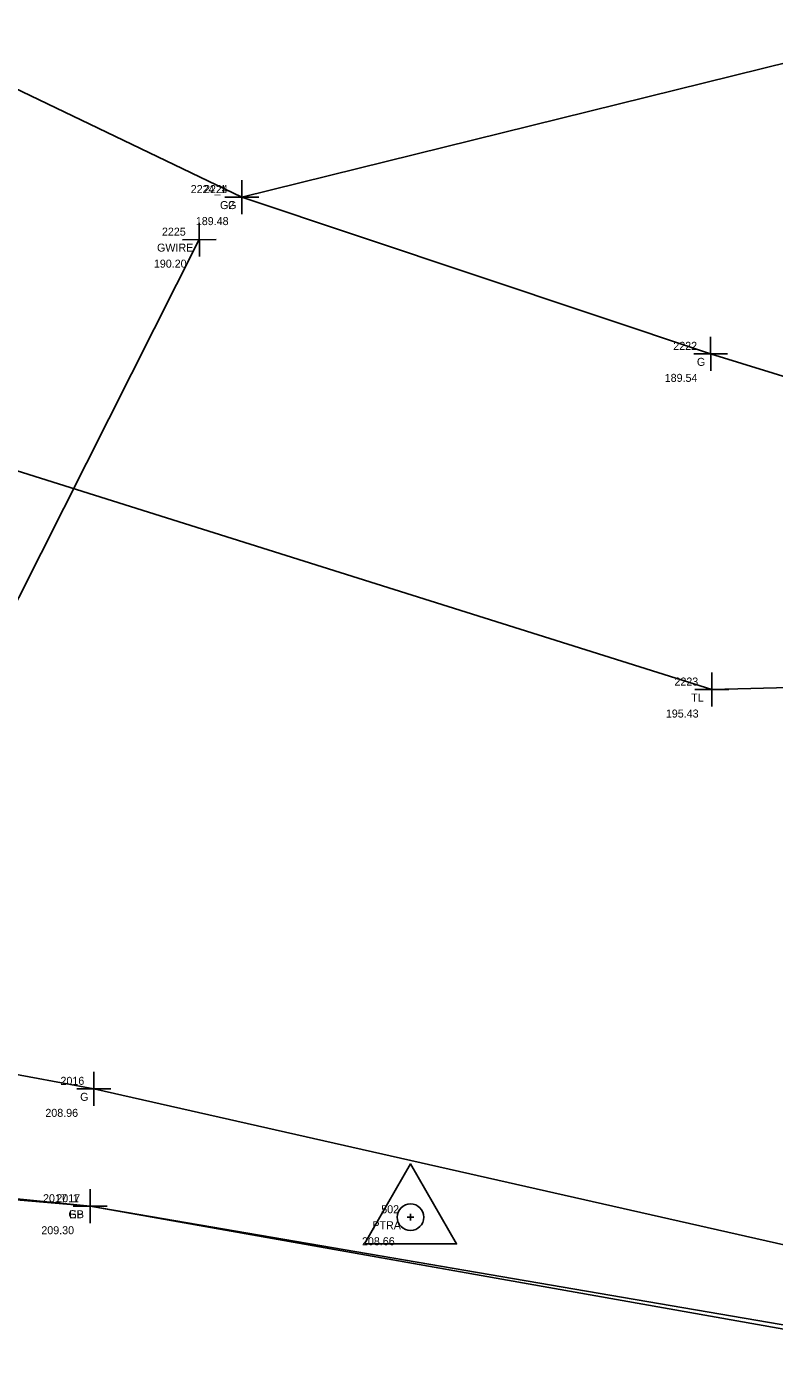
# Model space of a CAD drawing. Extents: x 1155460 to 1157069, y 590691 to 591363.
# Drawn here: x 1156504.2 to 1156532.2, y 591071.2 to 591121.6 of the extents above; entities that cross this region are included whole.
import ezdxf

# ---------------------------------------------------------------- set-up
doc = ezdxf.new("R2010")
doc.units = 0
for name, color, linetype in [('S_Control_Traverse_Point', 7, 'Continuous'), ('S_Field_Code', 7, 'Continuous'), ('S_Ground_Elevation', 7, 'Continuous'), ('S_Guardrail_Beam', 7, 'Continuous'), ('S_Point_Elevation', 7, 'Continuous'), ('S_Point_Name', 7, 'Continuous'), ('S_Roadway_Edge_Pavement', 7, 'Continuous'), ('S_Survey_Shot', 7, 'Continuous'), ('S_Trees_TreeLine', 7, 'Continuous'), ('S_Utilities_GuyWire3', 7, 'Continuous')]:
    doc.layers.add(name, color=color, linetype=linetype)

msp = doc.modelspace()

# ---------------------------------------------------------------- linework, layer by layer
at = {"layer": 'S_Control_Traverse_Point'}
for p, q in [((1156518.609, 591077.122), (1156518.609, 591076.873)), ((1156518.484, 591076.997), (1156518.734, 591076.997))]:
    msp.add_line(p, q, dxfattribs=at)
msp.add_lwpolyline([(1156516.88, 591075.999), (1156520.338, 591075.999), (1156518.609, 591078.993)], close=True, dxfattribs=at)
msp.add_circle((1156518.609, 591076.997), 0.499, dxfattribs=at)
at = {"layer": 'S_Ground_Elevation'}
for points in [[(1156994.312, 591026.354), (1156988.281, 591011.67), (1156982.157, 591006.699), (1156976.222, 591006.261), (1156935.59, 591012.529), (1156909.286, 591020.249), (1156879.276, 591021.544), (1156853.942, 591026.061), (1156816.445, 591035.649), (1156768.114, 591049.43), (1156727.412, 591060.658), (1156689.215, 591071.126), (1156661.947, 591076.437), (1156626.722, 591088.15), (1156604.058, 591089.806), (1156567.292, 591097.74), (1156529.864, 591109.36), (1156512.279, 591115.236), (1156500.524, 591120.875), (1156488.74, 591123.45), (1156482.404, 591123.727), (1156471.928, 591117.762)], [(1156611.683, 591102.465), (1156576.553, 591112.467), (1156533.986, 591120.597), (1156512.279, 591115.236)], [(1156491.913, 591082.79), (1156492.329, 591083.824), (1156495.048, 591083.957), (1156506.736, 591081.81), (1156549.796, 591072.079), (1156594.701, 591064.294), (1156643.47, 591053.992), (1156692.982, 591043.457), (1156741.529, 591033.483), (1156787.931, 591023.885), (1156837.64, 591013.684), (1156874.149, 591006.125), (1156886.147, 591007.107), (1156898.915, 591006.968), (1156908.962, 591008.2), (1156912.663, 591006.47), (1156934.598, 591002.519), (1156962.056, 590995.598), (1156977.261, 590993.461), (1156984.027, 590995.095), (1156994.336, 590998.898), (1156998.327, 591004.238), (1157007.944, 591024.295)]]:
    msp.add_lwpolyline(points, dxfattribs=at)
at = {"layer": 'S_Guardrail_Beam'}
msp.add_lwpolyline([(1156481.869, 591081.283), (1156494.59, 591078.6), (1156506.597, 591077.41), (1156549.743, 591070.029), (1156594.66, 591061.958), (1156643.746, 591051.962), (1156692.997, 591041.75), (1156740.961, 591032.095), (1156787.757, 591022.456), (1156837.395, 591011.945), (1156873.883, 591004.183), (1156883.647, 591002.789), (1156896.653, 591001.52), (1156903.637, 591001.645), (1156908.578, 591003.006)], dxfattribs=at)
at = {"layer": 'S_Roadway_Edge_Pavement'}
msp.add_lwpolyline([(1156481.735, 591081.07), (1156489.409, 591079.442), (1156494.61, 591078.457), (1156506.597, 591077.41), (1156549.576, 591069.784), (1156594.668, 591061.67), (1156643.299, 591051.737), (1156692.849, 591041.437), (1156740.745, 591031.573), (1156787.596, 591022.093), (1156837.369, 591011.662), (1156873.731, 591003.888), (1156883.52, 591002.412), (1156896.577, 591000.843), (1156903.209, 591001.187), (1156906.725, 591001.448), (1156912.328, 591002.901), (1156934.046, 590996.44), (1156960.261, 590988.118), (1156974.358, 590983.975), (1157002.341, 590977.221), (1157022.261, 590972.908), (1157044.277, 590968.579), (1157068.612, 590963.118)], dxfattribs=at)
at = {"layer": 'S_Survey_Shot'}
for p, q in [((1156512.281, 591114.6), (1156512.278, 591115.873)), ((1156512.281, 591114.6), (1156512.278, 591115.873)), ((1156511.643, 591115.235), (1156512.916, 591115.238)), ((1156511.643, 591115.235), (1156512.916, 591115.238)), ((1156512.279, 591115.236), (1156512.279, 591115.236)), ((1156512.279, 591115.236), (1156512.279, 591115.236)), ((1156510.69, 591113.005), (1156510.687, 591114.277)), ((1156510.052, 591113.639), (1156511.324, 591113.642)), ((1156510.688, 591113.641), (1156510.688, 591113.641)), ((1156529.865, 591108.724), (1156529.863, 591109.996)), ((1156529.228, 591109.359), (1156530.5, 591109.361)), ((1156529.864, 591109.36), (1156529.864, 591109.36)), ((1156529.908, 591096.14), (1156529.905, 591097.413)), ((1156529.27, 591096.775), (1156530.543, 591096.778)), ((1156529.906, 591096.777), (1156529.906, 591096.777)), ((1156506.737, 591081.174), (1156506.735, 591082.447)), ((1156506.1, 591081.809), (1156507.372, 591081.812)), ((1156506.736, 591081.81), (1156506.736, 591081.81)), ((1156506.598, 591076.774), (1156506.596, 591078.046)), ((1156506.598, 591076.774), (1156506.596, 591078.046)), ((1156505.961, 591077.409), (1156507.233, 591077.412)), ((1156505.961, 591077.409), (1156507.233, 591077.412)), ((1156506.597, 591077.41), (1156506.597, 591077.41)), ((1156506.597, 591077.41), (1156506.597, 591077.41))]:
    msp.add_line(p, q, dxfattribs=at)
at = {"layer": 'S_Trees_TreeLine'}
msp.add_lwpolyline([(1156626.722, 591088.15), (1156602.462, 591086.491), (1156567.292, 591097.74), (1156529.906, 591096.777), (1156492.135, 591108.667), (1156496.742, 591138.205), (1156511.563, 591158.025), (1156535.411, 591162.838)], dxfattribs=at)
at = {"layer": 'S_Utilities_GuyWire3'}
msp.add_line((1156510.688, 591113.641), (1156510.688, 591113.641), dxfattribs=at)
msp.add_lwpolyline([(1156510.688, 591113.641), (1156496.3, 591085.122)], dxfattribs=at)

# ---------------------------------------------------------------- texts
at = {"layer": 'S_Field_Code'}
for s, p in [('G2', (1156511.465, 591114.786)), ('G', (1156511.765, 591114.786)), ('GWIRE', (1156509.103, 591113.191)), ('G', (1156529.349, 591108.91)), ('TL', (1156529.134, 591096.327)), ('G', (1156506.221, 591081.36)), ('GB', (1156505.782, 591076.96)), ('EP', (1156505.81, 591076.96)), ('PTRA', (1156517.178, 591076.547))]:
    msp.add_text(s, height=0.3, dxfattribs=at).set_placement(p)
at = {"layer": 'S_Point_Elevation'}
for s, p in [('189.48', (1156510.558, 591114.186)), ('189.48', (1156510.558, 591114.186)), ('190.20', (1156508.985, 591112.591)), ('189.54', (1156528.142, 591108.31)), ('195.43', (1156528.185, 591095.727)), ('208.96', (1156504.915, 591080.76)), ('209.30', (1156504.764, 591076.36)), ('209.30', (1156504.764, 591076.36)), ('208.66', (1156516.788, 591075.947))]:
    msp.add_text(s, height=0.3, dxfattribs=at).set_placement(p)
at = {"layer": 'S_Point_Name'}
for s, p in [('2224_1', (1156510.366, 591115.386)), ('2224', (1156510.865, 591115.386)), ('2225', (1156509.287, 591113.791)), ('2222', (1156528.463, 591109.51)), ('2223', (1156528.506, 591096.927)), ('2016', (1156505.482, 591081.96)), ('2017_1', (1156504.828, 591077.56)), ('2017', (1156505.326, 591077.56)), ('502', (1156517.511, 591077.147))]:
    msp.add_text(s, height=0.3, dxfattribs=at).set_placement(p)

doc.saveas('drawing.dxf')
